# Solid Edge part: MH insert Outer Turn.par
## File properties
Author: Dan
Template: FH Insert .par
Last saved by: Dan
Revision: 20
Application: Solid Edge
Density: 7833.000 kg/m^3
Accuracy: 0.990
Material: Steel
Face Style: Steel
Fill Style: ANSI32(Steel)
Virtual Style: Machined steel
Coef. of Thermal Exp: 1.3e-05
Thermal Conductivity: 32.0
Specific Heat: 481.0
Modulus of Elasticity: 199947953000.0
Poisson's Ratio: 0.29
Yield Stress: 262000766.0
Ultimate Stress: 358527364.0
Elongation: 0.0
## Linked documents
FH Insert .par
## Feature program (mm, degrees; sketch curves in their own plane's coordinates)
part copy "CopiedPart_1"
sketch for "Hole_5" plane through (0, 0, -36) normal (0, 0, -1) x-axis (-1, 0, 0)
  hole centre (-39.8448, 16.1322) bore radius 2.4585
hole "Hole_5" finite
sketch for "unnamed Hole 1" plane through (0, 0, -36) normal (0, 0, -1) x-axis (-1, 0, 0)
hole "unnamed Hole 1" finite
sketch for "unnamed Hole 2" plane through (0, 0, -36) normal (0, 0, -1) x-axis (-1, 0, 0)
  hole centre (16.1322, 39.893) bore radius 2.4585
hole "unnamed Hole 2" finite
sketch for "unnamed Hole 3" plane through (0, 0, -36) normal (0, 0, -1) x-axis (-1, 0, 0)
  hole centre (39.893, -16.084) bore radius 2.4585
hole "unnamed Hole 3" finite
pattern "unnamed Pattern 1" of "Hole_5", "unnamed Hole 1", "unnamed Hole 2", "unnamed Hole 3"
delete holes assoc c "unnamed DeleteHolesAssocC 1"
delete faces "unnamed DeleteFaces 1"
delete holes assoc c "unnamed DeleteHolesAssocC 2"
sketch for "unnamed RevolvedProtrusion 1" plane through (0, 0, 0) normal (0, -1, 0) x-axis (1, 0, 0)
  line (58, -18.293) -> (41.25, -18.293)
  line (41.25, -18.293) -> (41.25, -15.944)
  arc centre (38.25, -15.944) radius 3 from (41.25, -15.944) to (35.25, -15.944) ccw
  line (35.25, -15.944) -> (35.25, -18.2931)
  line (35.25, -18.2931) -> (26.8948, -18.2931)
revolve "unnamed RevolvedProtrusion 1" add full turn 360 deg
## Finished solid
Body 1: solid body, 28 faces, 28 edges, 0 vertices.
  Faces by surface: cylinder 12, plane 12, torus 2, cone 1, spun 1
  Edges by curve: circle 28
Bounding box of the edges (mm; curved faces can reach further): 116.000 x 116.000 x 26.842, from (-58, -58, -36) to (58, 58, -9.1581).
Cylindrical faces by radius (mm): R18.8116 x1, R21.8198 x1, R26.8948 x1, R35.25 x1, R41.25 x1, R53 x1, R55.65 x2, R58 x4
Conical faces (half-angle, radius in mm at the cone's reference point): 2 deg R19.3388 x1
Toroidal faces (ring radius, tube radius in mm): R20.4107 r1.015 x1, R38.25 r3 x1
Planar faces by outward normal: +z 8, -z 4
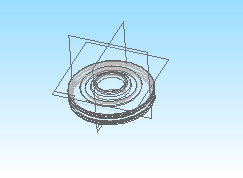
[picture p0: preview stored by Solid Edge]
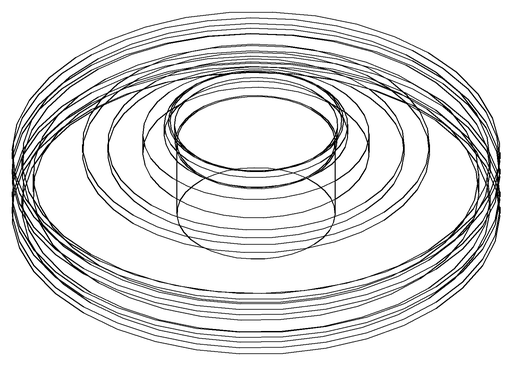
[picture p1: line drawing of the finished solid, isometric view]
